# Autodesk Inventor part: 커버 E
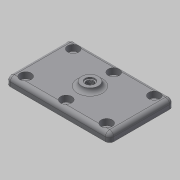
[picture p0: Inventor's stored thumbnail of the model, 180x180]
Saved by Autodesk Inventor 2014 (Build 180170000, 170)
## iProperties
Created: 2020-04
Part Number: 커버 E
Material: 알루미늄 6061
Document SubType Name: Modeling
Designer: mduedu
Density: 2.71 g/cm^3
Appearance: 기본값
Mass: 58.8274 g
Surface Area: 89.9592 cm^2
Volume: 21.7075 cm^3
Author: mduedu
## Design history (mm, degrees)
sketch "스케치1"
  geometry: L1 (37, 23)-(-37, 23); L2 (-37, 23)-(-37, -23); L3 (-37, -23)-(37, -23); L4 (37, -23)-(37, 23); L5 (37, 23)-(-37, -23); L6 (-37, 23)-(37, -23); 1 further point
  constraints: 12 end point, 2 midpoint, 2 parallel, 1 horizontal, 1 perpendicular
  dimensions: "d0" = 74 distance of L3.end L2.end; "d1" = 46 distance of L2.end L1.end
extrude "돌출1" new body sketch "스케치1" distance "d2" = 6; taper "d3" = 0 deg
sketch "스케치2"
  geometry: C1 r 6 at (0, 0); 1 further point
  constraints: 1 centre point, 1 coincident
  dimensions: "d4" = 12 diameter of C1
extrude "돌출2" join sketch "스케치2" distance "d5" = 3; taper "d6" = 0 deg
fillet "모깎기1" dims "d7" = 3
fillet "모깎기2" dims "d8" = 3
fillet "모깎기3" dims "d9" = 3
sketch "스케치3"
  geometry: L1 (-30, -13)-(30, -13); L2 (30, -13)-(30, 13); L3 (30, 13)-(-30, 13); L4 (-30, 13)-(-30, -13); L5 (-30, -13)-(30, 13); L6 (30, -13)-(-30, 13); 1 further point
  constraints: 12 end point, 2 midpoint, 2 parallel, 1 horizontal, 1 perpendicular
  dimensions: "d10" = 60 distance of L3.end L2.end; "d11" = 26 distance of L2.end L1.end
extrude "돌출3" join sketch "스케치3" distance "d12" = 2; taper "d13" = 0 deg
fillet "모깎기4" dims "d14" = 3
chamfer "모따기1" distance "d15" = 0.5; stored, may be unused: second distance "d16" = 2, angle "d17" = 45 deg
sketch "스케치4"
  geometry: L1 (-29, -17)-(29, -17); L2 (29, -17)-(29, 17); L3 (29, 17)-(-29, 17); L4 (-29, 17)-(-29, -17); L5 (-29, -17)-(29, 17); L6 (29, -17)-(-29, 17); 7 further points
  constraints: 12 end point, 4 coincident, 4 midpoint, 2 parallel, 1 horizontal, 1 perpendicular
  dimensions: "d18" = 58 distance of L3.end L2.end; "d19" = 34 distance of L2.end L1.end
hole "구멍1" sketch "스케치4" at (-29, 17), (-29, -17), (29, -17), (29, 17), (0, 17), (0, -17) diameter "d20" = 4.5; stored, may be unused: countersink angle "d24" = 90 deg, drill point angle "d26" = 118 deg; dims "d21" = 6, "d22" = 8, "d23" = 4.4, "d25" = 8
hole "구멍2" diameter "d29" = 5.188; stored, may be unused: countersink angle "d33" = 90 deg, drill point angle "d35" = 118 deg; dims "d27" = 10, "d28" = 10, "d30" = 6, "d31" = 8, "d32" = 4.4, "d34" = 8
sketch "스케치5"
  geometry: C1 r 3.5 at (0, 0); 1 further point
  constraints: 1 centre point, 1 coincident
  dimensions: "d36" = 7 diameter of C1
extrude "돌출4" cut sketch "스케치5" distance "d37" = 1; taper "d38" = 0 deg
node "솔리드1"
